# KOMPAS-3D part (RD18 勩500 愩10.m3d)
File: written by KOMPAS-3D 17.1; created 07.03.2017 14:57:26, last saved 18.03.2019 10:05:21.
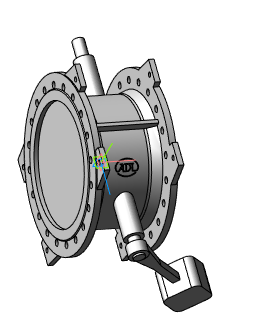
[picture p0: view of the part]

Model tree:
1. Операция без истории:2  (labels: Сталь 20  ГОСТ 1050-88)

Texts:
  RD18 Ду100 Ру16
  RD18 Ду150 Ру16
  RD18 Ду200 Ру16
  RD18 Ду250 Ру16
  RD18 Ду300 Ру16
  RD18 Ду350 Ру16
  RD18 Ду400 Ру10
  RD18 Ду400 Ру16
  RD18 Ду450 Ру10
  RD18 Ду450 Ру16
  RD18 Ду500 Ру10
  RD18 Ду500 Ру16
  RD18 Ду600 Ру10
  RD18 Ду600 Ру16
  RD18 Ду700 Ру10
  RD18 Ду700 Ру16
  RD18 Ду800 Ру10
  RD18 Ду800 Ру16
  RD18 Ду900 Ру10
  RD18 Ду900 Ру16
  RD18 Ду1000 Ру10
  RD18 Ду1000 Ру16
  RD18 Ду1200 Ру16
  RD18 Ду1400 Ру16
